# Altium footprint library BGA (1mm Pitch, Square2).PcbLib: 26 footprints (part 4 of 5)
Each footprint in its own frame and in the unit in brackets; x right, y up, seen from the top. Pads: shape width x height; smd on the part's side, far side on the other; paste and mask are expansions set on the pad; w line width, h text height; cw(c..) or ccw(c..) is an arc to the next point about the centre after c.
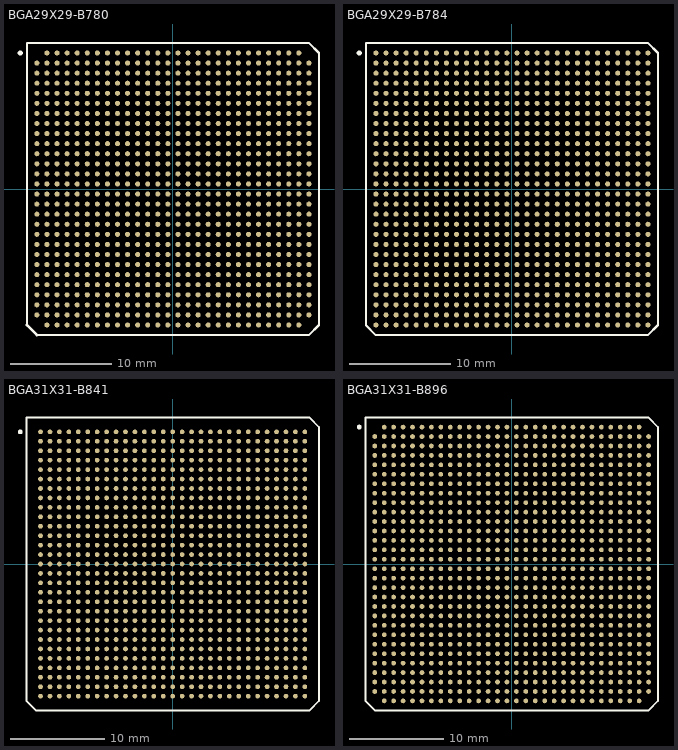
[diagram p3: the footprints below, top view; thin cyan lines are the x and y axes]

## BGA29X29-B780 [mm]
pads (780):
  round 0.5 smd: A2(-12.5,13.5) A3(-11.5,13.5) A4(-10.5,13.5) A5(-9.5,13.5) A6(-8.5,13.5) A7(-7.5,13.5) A8(-6.5,13.5) A9(-5.5,13.5) A10(-4.5,13.5) A11(-3.5,13.5) A12(-2.5,13.5) A13(-1.5,13.5) A14(-0.5,13.5) A15(0.5,13.5) A16(1.5,13.5) A17(2.5,13.5) A18(3.5,13.5) A19(4.5,13.5) A20(5.5,13.5) A21(6.5,13.5) A22(7.5,13.5) A23(8.5,13.5) A24(9.5,13.5) A25(10.5,13.5) A26(11.5,13.5) A27(12.5,13.5) AA1(-13.5,-6.5) AA2(-12.5,-6.5) AA3(-11.5,-6.5) AA4(-10.5,-6.5) AA5(-9.5,-6.5) AA6(-8.5,-6.5) AA7(-7.5,-6.5) AA8(-6.5,-6.5) AA9(-5.5,-6.5) AA10(-4.5,-6.5) AA11(-3.5,-6.5) AA12(-2.5,-6.5) AA13(-1.5,-6.5) AA14(-0.5,-6.5) AA15(0.5,-6.5) AA16(1.5,-6.5) AA17(2.5,-6.5) AA18(3.5,-6.5) AA19(4.5,-6.5) AA20(5.5,-6.5) AA21(6.5,-6.5) AA22(7.5,-6.5) AA23(8.5,-6.5) AA24(9.5,-6.5) AA25(10.5,-6.5) AA26(11.5,-6.5) AA27(12.5,-6.5) AA28(13.5,-6.5) AB1(-13.5,-7.5) AB2(-12.5,-7.5) AB3(-11.5,-7.5) AB4(-10.5,-7.5) AB5(-9.5,-7.5) AB6(-8.5,-7.5) AB7(-7.5,-7.5) AB8(-6.5,-7.5) AB9(-5.5,-7.5) AB10(-4.5,-7.5) AB11(-3.5,-7.5) AB12(-2.5,-7.5) AB13(-1.5,-7.5) AB14(-0.5,-7.5) AB15(0.5,-7.5) AB16(1.5,-7.5) AB17(2.5,-7.5) AB18(3.5,-7.5) AB19(4.5,-7.5) AB20(5.5,-7.5) AB21(6.5,-7.5) AB22(7.5,-7.5) AB23(8.5,-7.5) AB24(9.5,-7.5) AB25(10.5,-7.5) AB26(11.5,-7.5) AB27(12.5,-7.5) AB28(13.5,-7.5) AC1(-13.5,-8.5) AC2(-12.5,-8.5) AC3(-11.5,-8.5) AC4(-10.5,-8.5) AC5(-9.5,-8.5) AC6(-8.5,-8.5) AC7(-7.5,-8.5) AC8(-6.5,-8.5) AC9(-5.5,-8.5) AC10(-4.5,-8.5) AC11(-3.5,-8.5) AC12(-2.5,-8.5) AC13(-1.5,-8.5) AC14(-0.5,-8.5) AC15(0.5,-8.5) AC16(1.5,-8.5) AC17(2.5,-8.5) AC18(3.5,-8.5) AC19(4.5,-8.5) AC20(5.5,-8.5) AC21(6.5,-8.5) AC22(7.5,-8.5) AC23(8.5,-8.5) AC24(9.5,-8.5) AC25(10.5,-8.5) AC26(11.5,-8.5) AC27(12.5,-8.5) AC28(13.5,-8.5) AD1(-13.5,-9.5) AD2(-12.5,-9.5) AD3(-11.5,-9.5) AD4(-10.5,-9.5) AD5(-9.5,-9.5) AD6(-8.5,-9.5) AD7(-7.5,-9.5) AD8(-6.5,-9.5) AD9(-5.5,-9.5) AD10(-4.5,-9.5) AD11(-3.5,-9.5) AD12(-2.5,-9.5) AD13(-1.5,-9.5) AD14(-0.5,-9.5) AD15(0.5,-9.5) AD16(1.5,-9.5) AD17(2.5,-9.5) AD18(3.5,-9.5) AD19(4.5,-9.5) AD20(5.5,-9.5) AD21(6.5,-9.5) AD22(7.5,-9.5) AD23(8.5,-9.5) AD24(9.5,-9.5) AD25(10.5,-9.5) AD26(11.5,-9.5) AD27(12.5,-9.5) AD28(13.5,-9.5) AE1(-13.5,-10.5) AE2(-12.5,-10.5) AE3(-11.5,-10.5) AE4(-10.5,-10.5) AE5(-9.5,-10.5) AE6(-8.5,-10.5) AE7(-7.5,-10.5) AE8(-6.5,-10.5) AE9(-5.5,-10.5) AE10(-4.5,-10.5) AE11(-3.5,-10.5) AE12(-2.5,-10.5) AE13(-1.5,-10.5) AE14(-0.5,-10.5) AE15(0.5,-10.5) AE16(1.5,-10.5) AE17(2.5,-10.5) AE18(3.5,-10.5) AE19(4.5,-10.5) AE20(5.5,-10.5) AE21(6.5,-10.5) AE22(7.5,-10.5) AE23(8.5,-10.5) AE24(9.5,-10.5) AE25(10.5,-10.5) AE26(11.5,-10.5) AE27(12.5,-10.5) AE28(13.5,-10.5) AF1(-13.5,-11.5) AF2(-12.5,-11.5) AF3(-11.5,-11.5) AF4(-10.5,-11.5) AF5(-9.5,-11.5) AF6(-8.5,-11.5) AF7(-7.5,-11.5) AF8(-6.5,-11.5) AF9(-5.5,-11.5) AF10(-4.5,-11.5) AF11(-3.5,-11.5) AF12(-2.5,-11.5) AF13(-1.5,-11.5) AF14(-0.5,-11.5) AF15(0.5,-11.5) AF16(1.5,-11.5) AF17(2.5,-11.5) AF18(3.5,-11.5) AF19(4.5,-11.5) AF20(5.5,-11.5) AF21(6.5,-11.5) AF22(7.5,-11.5) AF23(8.5,-11.5) AF24(9.5,-11.5) AF25(10.5,-11.5) AF26(11.5,-11.5) AF27(12.5,-11.5) AF28(13.5,-11.5) AG1(-13.5,-12.5) AG2(-12.5,-12.5) AG3(-11.5,-12.5) AG4(-10.5,-12.5) AG5(-9.5,-12.5) AG6(-8.5,-12.5) AG7(-7.5,-12.5) AG8(-6.5,-12.5) AG9(-5.5,-12.5) AG10(-4.5,-12.5) AG11(-3.5,-12.5) AG12(-2.5,-12.5) AG13(-1.5,-12.5) AG14(-0.5,-12.5) AG15(0.5,-12.5) AG16(1.5,-12.5) AG17(2.5,-12.5) AG18(3.5,-12.5) AG19(4.5,-12.5) AG20(5.5,-12.5) AG21(6.5,-12.5) AG22(7.5,-12.5) AG23(8.5,-12.5) AG24(9.5,-12.5) AG25(10.5,-12.5) AG26(11.5,-12.5) AG27(12.5,-12.5) AG28(13.5,-12.5) AH2(-12.5,-13.5) AH3(-11.5,-13.5) AH4(-10.5,-13.5) AH5(-9.5,-13.5) AH6(-8.5,-13.5) AH7(-7.5,-13.5) AH8(-6.5,-13.5) AH9(-5.5,-13.5) AH10(-4.5,-13.5) AH11(-3.5,-13.5) AH12(-2.5,-13.5) AH13(-1.5,-13.5) AH14(-0.5,-13.5) AH15(0.5,-13.5) AH16(1.5,-13.5) AH17(2.5,-13.5) AH18(3.5,-13.5) AH19(4.5,-13.5) AH20(5.5,-13.5) AH21(6.5,-13.5) AH22(7.5,-13.5) AH23(8.5,-13.5) AH24(9.5,-13.5) AH25(10.5,-13.5) AH26(11.5,-13.5) AH27(12.5,-13.5) B1(-13.5,12.5) B2(-12.5,12.5) B3(-11.5,12.5) B4(-10.5,12.5) B5(-9.5,12.5) B6(-8.5,12.5) B7(-7.5,12.5) B8(-6.5,12.5) B9(-5.5,12.5) B10(-4.5,12.5) B11(-3.5,12.5) B12(-2.5,12.5) B13(-1.5,12.5) B14(-0.5,12.5) B15(0.5,12.5) B16(1.5,12.5) B17(2.5,12.5) B18(3.5,12.5) B19(4.5,12.5) B20(5.5,12.5) B21(6.5,12.5) B22(7.5,12.5) B23(8.5,12.5) B24(9.5,12.5) B25(10.5,12.5) B26(11.5,12.5) B27(12.5,12.5) B28(13.5,12.5) C1(-13.5,11.5) C2(-12.5,11.5) C3(-11.5,11.5) C4(-10.5,11.5) C5(-9.5,11.5) C6(-8.5,11.5) C7(-7.5,11.5) C8(-6.5,11.5) C9(-5.5,11.5) C10(-4.5,11.5) C11(-3.5,11.5) C12(-2.5,11.5) C13(-1.5,11.5) C14(-0.5,11.5) C15(0.5,11.5) C16(1.5,11.5) C17(2.5,11.5) C18(3.5,11.5) C19(4.5,11.5) C20(5.5,11.5) C21(6.5,11.5) C22(7.5,11.5) C23(8.5,11.5) C24(9.5,11.5) C25(10.5,11.5) C26(11.5,11.5) C27(12.5,11.5) C28(13.5,11.5) D1(-13.5,10.5) D2(-12.5,10.5) D3(-11.5,10.5) D4(-10.5,10.5) D5(-9.5,10.5) D6(-8.5,10.5) D7(-7.5,10.5) D8(-6.5,10.5) D9(-5.5,10.5) D10(-4.5,10.5) D11(-3.5,10.5) D12(-2.5,10.5) D13(-1.5,10.5) D14(-0.5,10.5) D15(0.5,10.5) D16(1.5,10.5) D17(2.5,10.5) D18(3.5,10.5) D19(4.5,10.5) D20(5.5,10.5) D21(6.5,10.5) D22(7.5,10.5) D23(8.5,10.5) D24(9.5,10.5) D25(10.5,10.5) D26(11.5,10.5) D27(12.5,10.5) D28(13.5,10.5) E1(-13.5,9.5) E2(-12.5,9.5) E3(-11.5,9.5) E4(-10.5,9.5) E5(-9.5,9.5) E6(-8.5,9.5) E7(-7.5,9.5) E8(-6.5,9.5) E9(-5.5,9.5) E10(-4.5,9.5) E11(-3.5,9.5) E12(-2.5,9.5) E13(-1.5,9.5) E14(-0.5,9.5) E15(0.5,9.5) E16(1.5,9.5) E17(2.5,9.5) E18(3.5,9.5) E19(4.5,9.5) E20(5.5,9.5) E21(6.5,9.5) E22(7.5,9.5) E23(8.5,9.5) E24(9.5,9.5) E25(10.5,9.5) E26(11.5,9.5) E27(12.5,9.5) E28(13.5,9.5) F1(-13.5,8.5) F2(-12.5,8.5) F3(-11.5,8.5) F4(-10.5,8.5) F5(-9.5,8.5) F6(-8.5,8.5) F7(-7.5,8.5) F8(-6.5,8.5) F9(-5.5,8.5) F10(-4.5,8.5) F11(-3.5,8.5) F12(-2.5,8.5) F13(-1.5,8.5) F14(-0.5,8.5) F15(0.5,8.5) F16(1.5,8.5) F17(2.5,8.5) F18(3.5,8.5) F19(4.5,8.5) F20(5.5,8.5) F21(6.5,8.5) F22(7.5,8.5) F23(8.5,8.5) F24(9.5,8.5) F25(10.5,8.5) F26(11.5,8.5) F27(12.5,8.5) F28(13.5,8.5) G1(-13.5,7.5) G2(-12.5,7.5) G3(-11.5,7.5) G4(-10.5,7.5) G5(-9.5,7.5) G6(-8.5,7.5) G7(-7.5,7.5) G8(-6.5,7.5) G9(-5.5,7.5) G10(-4.5,7.5) G11(-3.5,7.5) G12(-2.5,7.5) G13(-1.5,7.5) G14(-0.5,7.5) G15(0.5,7.5) G16(1.5,7.5) G17(2.5,7.5) G18(3.5,7.5) G19(4.5,7.5) G20(5.5,7.5) G21(6.5,7.5) G22(7.5,7.5) G23(8.5,7.5) G24(9.5,7.5) G25(10.5,7.5) G26(11.5,7.5) G27(12.5,7.5) G28(13.5,7.5) H1(-13.5,6.5) H2(-12.5,6.5) H3(-11.5,6.5) H4(-10.5,6.5) H5(-9.5,6.5) H6(-8.5,6.5) H7(-7.5,6.5) H8(-6.5,6.5) H9(-5.5,6.5) H10(-4.5,6.5) H11(-3.5,6.5) H12(-2.5,6.5) H13(-1.5,6.5) H14(-0.5,6.5) H15(0.5,6.5) H16(1.5,6.5) H17(2.5,6.5) H18(3.5,6.5) H19(4.5,6.5) H20(5.5,6.5) H21(6.5,6.5) H22(7.5,6.5) H23(8.5,6.5) H24(9.5,6.5) H25(10.5,6.5) H26(11.5,6.5) H27(12.5,6.5) H28(13.5,6.5) J1(-13.5,5.5) J2(-12.5,5.5) J3(-11.5,5.5) J4(-10.5,5.5) J5(-9.5,5.5) J6(-8.5,5.5) J7(-7.5,5.5) J8(-6.5,5.5) J9(-5.5,5.5) J10(-4.5,5.5) J11(-3.5,5.5) J12(-2.5,5.5) J13(-1.5,5.5) J14(-0.5,5.5) J15(0.5,5.5) J16(1.5,5.5) J17(2.5,5.5) J18(3.5,5.5) J19(4.5,5.5) J20(5.5,5.5) J21(6.5,5.5) J22(7.5,5.5) J23(8.5,5.5) J24(9.5,5.5) J25(10.5,5.5) J26(11.5,5.5) J27(12.5,5.5) J28(13.5,5.5) K1(-13.5,4.5) K2(-12.5,4.5) K3(-11.5,4.5) K4(-10.5,4.5) K5(-9.5,4.5) K6(-8.5,4.5) K7(-7.5,4.5) K8(-6.5,4.5) K9(-5.5,4.5) K10(-4.5,4.5) K11(-3.5,4.5) K12(-2.5,4.5) K13(-1.5,4.5) K14(-0.5,4.5) K15(0.5,4.5) K16(1.5,4.5) K17(2.5,4.5) K18(3.5,4.5) K19(4.5,4.5) K20(5.5,4.5) K21(6.5,4.5) K22(7.5,4.5) K23(8.5,4.5) K24(9.5,4.5) K25(10.5,4.5) K26(11.5,4.5) K27(12.5,4.5) K28(13.5,4.5) L1(-13.5,3.5) L2(-12.5,3.5) L3(-11.5,3.5) L4(-10.5,3.5) L5(-9.5,3.5) L6(-8.5,3.5) L7(-7.5,3.5) L8(-6.5,3.5) L9(-5.5,3.5) L10(-4.5,3.5) L11(-3.5,3.5) L12(-2.5,3.5) L13(-1.5,3.5) L14(-0.5,3.5) L15(0.5,3.5) L16(1.5,3.5) L17(2.5,3.5) L18(3.5,3.5) L19(4.5,3.5) L20(5.5,3.5) L21(6.5,3.5) L22(7.5,3.5) L23(8.5,3.5) L24(9.5,3.5) L25(10.5,3.5) L26(11.5,3.5) L27(12.5,3.5) L28(13.5,3.5) M1(-13.5,2.5) M2(-12.5,2.5) M3(-11.5,2.5) M4(-10.5,2.5) M5(-9.5,2.5) M6(-8.5,2.5) M7(-7.5,2.5) M8(-6.5,2.5) M9(-5.5,2.5) M10(-4.5,2.5) M11(-3.5,2.5) M12(-2.5,2.5) M13(-1.5,2.5) M14(-0.5,2.5) M15(0.5,2.5) M16(1.5,2.5) M17(2.5,2.5) M18(3.5,2.5) M19(4.5,2.5) M20(5.5,2.5) M21(6.5,2.5) M22(7.5,2.5) M23(8.5,2.5) M24(9.5,2.5) M25(10.5,2.5) M26(11.5,2.5) M27(12.5,2.5) M28(13.5,2.5) N1(-13.5,1.5) N2(-12.5,1.5) N3(-11.5,1.5) N4(-10.5,1.5) N5(-9.5,1.5) N6(-8.5,1.5) N7(-7.5,1.5) N8(-6.5,1.5) N9(-5.5,1.5) N10(-4.5,1.5) N11(-3.5,1.5) N12(-2.5,1.5) N13(-1.5,1.5) N14(-0.5,1.5) N15(0.5,1.5) N16(1.5,1.5) N17(2.5,1.5) N18(3.5,1.5) N19(4.5,1.5) N20(5.5,1.5) N21(6.5,1.5) N22(7.5,1.5) N23(8.5,1.5) N24(9.5,1.5) N25(10.5,1.5) N26(11.5,1.5) N27(12.5,1.5) N28(13.5,1.5) P1(-13.5,0.5) P2(-12.5,0.5) P3(-11.5,0.5) P4(-10.5,0.5) P5(-9.5,0.5) P6(-8.5,0.5) P7(-7.5,0.5) P8(-6.5,0.5) P9(-5.5,0.5) P10(-4.5,0.5) P11(-3.5,0.5) P12(-2.5,0.5) P13(-1.5,0.5) P14(-0.5,0.5) P15(0.5,0.5) P16(1.5,0.5) P17(2.5,0.5) P18(3.5,0.5) P19(4.5,0.5) P20(5.5,0.5) P21(6.5,0.5) P22(7.5,0.5) P23(8.5,0.5) P24(9.5,0.5) P25(10.5,0.5) P26(11.5,0.5) P27(12.5,0.5) P28(13.5,0.5) R1(-13.5,-0.5) R2(-12.5,-0.5) R3(-11.5,-0.5) R4(-10.5,-0.5) R5(-9.5,-0.5) R6(-8.5,-0.5) R7(-7.5,-0.5) R8(-6.5,-0.5) R9(-5.5,-0.5) R10(-4.5,-0.5) R11(-3.5,-0.5) R12(-2.5,-0.5) R13(-1.5,-0.5) R14(-0.5,-0.5) R15(0.5,-0.5) R16(1.5,-0.5) R17(2.5,-0.5) R18(3.5,-0.5) R19(4.5,-0.5) R20(5.5,-0.5) R21(6.5,-0.5) R22(7.5,-0.5) R23(8.5,-0.5) R24(9.5,-0.5) R25(10.5,-0.5) R26(11.5,-0.5) R27(12.5,-0.5) R28(13.5,-0.5) T1(-13.5,-1.5) T2(-12.5,-1.5) T3(-11.5,-1.5) T4(-10.5,-1.5) T5(-9.5,-1.5) T6(-8.5,-1.5) T7(-7.5,-1.5) T8(-6.5,-1.5) T9(-5.5,-1.5) T10(-4.5,-1.5) T11(-3.5,-1.5) T12(-2.5,-1.5) T13(-1.5,-1.5) T14(-0.5,-1.5) T15(0.5,-1.5) T16(1.5,-1.5) T17(2.5,-1.5) T18(3.5,-1.5) T19(4.5,-1.5) T20(5.5,-1.5) T21(6.5,-1.5) T22(7.5,-1.5) T23(8.5,-1.5) T24(9.5,-1.5) T25(10.5,-1.5) T26(11.5,-1.5) T27(12.5,-1.5) T28(13.5,-1.5) U1(-13.5,-2.5) U2(-12.5,-2.5) U3(-11.5,-2.5) U4(-10.5,-2.5) U5(-9.5,-2.5) U6(-8.5,-2.5) U7(-7.5,-2.5) U8(-6.5,-2.5) U9(-5.5,-2.5) U10(-4.5,-2.5) U11(-3.5,-2.5) U12(-2.5,-2.5) U13(-1.5,-2.5) U14(-0.5,-2.5) U15(0.5,-2.5) U16(1.5,-2.5) U17(2.5,-2.5) U18(3.5,-2.5) U19(4.5,-2.5) U20(5.5,-2.5) U21(6.5,-2.5) U22(7.5,-2.5) U23(8.5,-2.5) U24(9.5,-2.5) U25(10.5,-2.5) U26(11.5,-2.5) U27(12.5,-2.5) U28(13.5,-2.5) V1(-13.5,-3.5) V2(-12.5,-3.5) V3(-11.5,-3.5) V4(-10.5,-3.5) V5(-9.5,-3.5) V6(-8.5,-3.5) V7(-7.5,-3.5) V8(-6.5,-3.5) V9(-5.5,-3.5) V10(-4.5,-3.5) V11(-3.5,-3.5) V12(-2.5,-3.5) V13(-1.5,-3.5) V14(-0.5,-3.5) V15(0.5,-3.5) V16(1.5,-3.5) V17(2.5,-3.5) V18(3.5,-3.5) V19(4.5,-3.5) V20(5.5,-3.5) V21(6.5,-3.5) V22(7.5,-3.5) V23(8.5,-3.5) V24(9.5,-3.5) V25(10.5,-3.5) V26(11.5,-3.5) V27(12.5,-3.5) V28(13.5,-3.5) W1(-13.5,-4.5) W2(-12.5,-4.5) W3(-11.5,-4.5) W4(-10.5,-4.5) W5(-9.5,-4.5) W6(-8.5,-4.5) W7(-7.5,-4.5) W8(-6.5,-4.5) W9(-5.5,-4.5) W10(-4.5,-4.5) W11(-3.5,-4.5) W12(-2.5,-4.5) W13(-1.5,-4.5) W14(-0.5,-4.5) W15(0.5,-4.5) W16(1.5,-4.5) W17(2.5,-4.5) W18(3.5,-4.5) W19(4.5,-4.5) W20(5.5,-4.5) W21(6.5,-4.5) W22(7.5,-4.5) W23(8.5,-4.5) W24(9.5,-4.5) W25(10.5,-4.5) W26(11.5,-4.5) W27(12.5,-4.5) W28(13.5,-4.5) Y1(-13.5,-5.5) Y2(-12.5,-5.5) Y3(-11.5,-5.5) Y4(-10.5,-5.5) Y5(-9.5,-5.5) Y6(-8.5,-5.5) Y7(-7.5,-5.5) Y8(-6.5,-5.5) Y9(-5.5,-5.5) Y10(-4.5,-5.5) Y11(-3.5,-5.5) Y12(-2.5,-5.5) Y13(-1.5,-5.5) Y14(-0.5,-5.5) Y15(0.5,-5.5) Y16(1.5,-5.5) Y17(2.5,-5.5) Y18(3.5,-5.5) Y19(4.5,-5.5) Y20(5.5,-5.5) Y21(6.5,-5.5) Y22(7.5,-5.5) Y23(8.5,-5.5) Y24(9.5,-5.5) Y25(10.5,-5.5) Y26(11.5,-5.5) Y27(12.5,-5.5) Y28(13.5,-5.5)
Top Overlay:
  circle w0.25: c-15.15,13.5 r0.125
  lines w0.2: -14.5,-13.5 -14.5,14.5 13.5,14.5 14.5,13.5 14.5,-13.5 13.5,-14.5 -13.5,-14.5
  lines w0.254: -14.5,-13.5 -13.5,-14.5

## BGA29X29-B784 [mm]
pads (784):
  round 0.5 smd: A1(-13.5,13.5) A2(-12.5,13.5) A3(-11.5,13.5) A4(-10.5,13.5) A5(-9.5,13.5) A6(-8.5,13.5) A7(-7.5,13.5) A8(-6.5,13.5) A9(-5.5,13.5) A10(-4.5,13.5) A11(-3.5,13.5) A12(-2.5,13.5) A13(-1.5,13.5) A14(-0.5,13.5) A15(0.5,13.5) A16(1.5,13.5) A17(2.5,13.5) A18(3.5,13.5) A19(4.5,13.5) A20(5.5,13.5) A21(6.5,13.5) A22(7.5,13.5) A23(8.5,13.5) A24(9.5,13.5) A25(10.5,13.5) A26(11.5,13.5) A27(12.5,13.5) A28(13.5,13.5) AA1(-13.5,-6.5) AA2(-12.5,-6.5) AA3(-11.5,-6.5) AA4(-10.5,-6.5) AA5(-9.5,-6.5) AA6(-8.5,-6.5) AA7(-7.5,-6.5) AA8(-6.5,-6.5) AA9(-5.5,-6.5) AA10(-4.5,-6.5) AA11(-3.5,-6.5) AA12(-2.5,-6.5) AA13(-1.5,-6.5) AA14(-0.5,-6.5) AA15(0.5,-6.5) AA16(1.5,-6.5) AA17(2.5,-6.5) AA18(3.5,-6.5) AA19(4.5,-6.5) AA20(5.5,-6.5) AA21(6.5,-6.5) AA22(7.5,-6.5) AA23(8.5,-6.5) AA24(9.5,-6.5) AA25(10.5,-6.5) AA26(11.5,-6.5) AA27(12.5,-6.5) AA28(13.5,-6.5) AB1(-13.5,-7.5) AB2(-12.5,-7.5) AB3(-11.5,-7.5) AB4(-10.5,-7.5) AB5(-9.5,-7.5) AB6(-8.5,-7.5) AB7(-7.5,-7.5) AB8(-6.5,-7.5) AB9(-5.5,-7.5) AB10(-4.5,-7.5) AB11(-3.5,-7.5) AB12(-2.5,-7.5) AB13(-1.5,-7.5) AB14(-0.5,-7.5) AB15(0.5,-7.5) AB16(1.5,-7.5) AB17(2.5,-7.5) AB18(3.5,-7.5) AB19(4.5,-7.5) AB20(5.5,-7.5) AB21(6.5,-7.5) AB22(7.5,-7.5) AB23(8.5,-7.5) AB24(9.5,-7.5) AB25(10.5,-7.5) AB26(11.5,-7.5) AB27(12.5,-7.5) AB28(13.5,-7.5) AC1(-13.5,-8.5) AC2(-12.5,-8.5) AC3(-11.5,-8.5) AC4(-10.5,-8.5) AC5(-9.5,-8.5) AC6(-8.5,-8.5) AC7(-7.5,-8.5) AC8(-6.5,-8.5) AC9(-5.5,-8.5) AC10(-4.5,-8.5) AC11(-3.5,-8.5) AC12(-2.5,-8.5) AC13(-1.5,-8.5) AC14(-0.5,-8.5) AC15(0.5,-8.5) AC16(1.5,-8.5) AC17(2.5,-8.5) AC18(3.5,-8.5) AC19(4.5,-8.5) AC20(5.5,-8.5) AC21(6.5,-8.5) AC22(7.5,-8.5) AC23(8.5,-8.5) AC24(9.5,-8.5) AC25(10.5,-8.5) AC26(11.5,-8.5) AC27(12.5,-8.5) AC28(13.5,-8.5) AD1(-13.5,-9.5) AD2(-12.5,-9.5) AD3(-11.5,-9.5) AD4(-10.5,-9.5) AD5(-9.5,-9.5) AD6(-8.5,-9.5) AD7(-7.5,-9.5) AD8(-6.5,-9.5) AD9(-5.5,-9.5) AD10(-4.5,-9.5) AD11(-3.5,-9.5) AD12(-2.5,-9.5) AD13(-1.5,-9.5) AD14(-0.5,-9.5) AD15(0.5,-9.5) AD16(1.5,-9.5) AD17(2.5,-9.5) AD18(3.5,-9.5) AD19(4.5,-9.5) AD20(5.5,-9.5) AD21(6.5,-9.5) AD22(7.5,-9.5) AD23(8.5,-9.5) AD24(9.5,-9.5) AD25(10.5,-9.5) AD26(11.5,-9.5) AD27(12.5,-9.5) AD28(13.5,-9.5) AE1(-13.5,-10.5) AE2(-12.5,-10.5) AE3(-11.5,-10.5) AE4(-10.5,-10.5) AE5(-9.5,-10.5) AE6(-8.5,-10.5) AE7(-7.5,-10.5) AE8(-6.5,-10.5) AE9(-5.5,-10.5) AE10(-4.5,-10.5) AE11(-3.5,-10.5) AE12(-2.5,-10.5) AE13(-1.5,-10.5) AE14(-0.5,-10.5) AE15(0.5,-10.5) AE16(1.5,-10.5) AE17(2.5,-10.5) AE18(3.5,-10.5) AE19(4.5,-10.5) AE20(5.5,-10.5) AE21(6.5,-10.5) AE22(7.5,-10.5) AE23(8.5,-10.5) AE24(9.5,-10.5) AE25(10.5,-10.5) AE26(11.5,-10.5) AE27(12.5,-10.5) AE28(13.5,-10.5) AF1(-13.5,-11.5) AF2(-12.5,-11.5) AF3(-11.5,-11.5) AF4(-10.5,-11.5) AF5(-9.5,-11.5) AF6(-8.5,-11.5) AF7(-7.5,-11.5) AF8(-6.5,-11.5) AF9(-5.5,-11.5) AF10(-4.5,-11.5) AF11(-3.5,-11.5) AF12(-2.5,-11.5) AF13(-1.5,-11.5) AF14(-0.5,-11.5) AF15(0.5,-11.5) AF16(1.5,-11.5) AF17(2.5,-11.5) AF18(3.5,-11.5) AF19(4.5,-11.5) AF20(5.5,-11.5) AF21(6.5,-11.5) AF22(7.5,-11.5) AF23(8.5,-11.5) AF24(9.5,-11.5) AF25(10.5,-11.5) AF26(11.5,-11.5) AF27(12.5,-11.5) AF28(13.5,-11.5) AG1(-13.5,-12.5) AG2(-12.5,-12.5) AG3(-11.5,-12.5) AG4(-10.5,-12.5) AG5(-9.5,-12.5) AG6(-8.5,-12.5) AG7(-7.5,-12.5) AG8(-6.5,-12.5) AG9(-5.5,-12.5) AG10(-4.5,-12.5) AG11(-3.5,-12.5) AG12(-2.5,-12.5) AG13(-1.5,-12.5) AG14(-0.5,-12.5) AG15(0.5,-12.5) AG16(1.5,-12.5) AG17(2.5,-12.5) AG18(3.5,-12.5) AG19(4.5,-12.5) AG20(5.5,-12.5) AG21(6.5,-12.5) AG22(7.5,-12.5) AG23(8.5,-12.5) AG24(9.5,-12.5) AG25(10.5,-12.5) AG26(11.5,-12.5) AG27(12.5,-12.5) AG28(13.5,-12.5) AH1(-13.5,-13.5) AH2(-12.5,-13.5) AH3(-11.5,-13.5) AH4(-10.5,-13.5) AH5(-9.5,-13.5) AH6(-8.5,-13.5) AH7(-7.5,-13.5) AH8(-6.5,-13.5) AH9(-5.5,-13.5) AH10(-4.5,-13.5) AH11(-3.5,-13.5) AH12(-2.5,-13.5) AH13(-1.5,-13.5) AH14(-0.5,-13.5) AH15(0.5,-13.5) AH16(1.5,-13.5) AH17(2.5,-13.5) AH18(3.5,-13.5) AH19(4.5,-13.5) AH20(5.5,-13.5) AH21(6.5,-13.5) AH22(7.5,-13.5) AH23(8.5,-13.5) AH24(9.5,-13.5) AH25(10.5,-13.5) AH26(11.5,-13.5) AH27(12.5,-13.5) AH28(13.5,-13.5) B1(-13.5,12.5) B2(-12.5,12.5) B3(-11.5,12.5) B4(-10.5,12.5) B5(-9.5,12.5) B6(-8.5,12.5) B7(-7.5,12.5) B8(-6.5,12.5) B9(-5.5,12.5) B10(-4.5,12.5) B11(-3.5,12.5) B12(-2.5,12.5) B13(-1.5,12.5) B14(-0.5,12.5) B15(0.5,12.5) B16(1.5,12.5) B17(2.5,12.5) B18(3.5,12.5) B19(4.5,12.5) B20(5.5,12.5) B21(6.5,12.5) B22(7.5,12.5) B23(8.5,12.5) B24(9.5,12.5) B25(10.5,12.5) B26(11.5,12.5) B27(12.5,12.5) B28(13.5,12.5) C1(-13.5,11.5) C2(-12.5,11.5) C3(-11.5,11.5) C4(-10.5,11.5) C5(-9.5,11.5) C6(-8.5,11.5) C7(-7.5,11.5) C8(-6.5,11.5) C9(-5.5,11.5) C10(-4.5,11.5) C11(-3.5,11.5) C12(-2.5,11.5) C13(-1.5,11.5) C14(-0.5,11.5) C15(0.5,11.5) C16(1.5,11.5) C17(2.5,11.5) C18(3.5,11.5) C19(4.5,11.5) C20(5.5,11.5) C21(6.5,11.5) C22(7.5,11.5) C23(8.5,11.5) C24(9.5,11.5) C25(10.5,11.5) C26(11.5,11.5) C27(12.5,11.5) C28(13.5,11.5) D1(-13.5,10.5) D2(-12.5,10.5) D3(-11.5,10.5) D4(-10.5,10.5) D5(-9.5,10.5) D6(-8.5,10.5) D7(-7.5,10.5) D8(-6.5,10.5) D9(-5.5,10.5) D10(-4.5,10.5) D11(-3.5,10.5) D12(-2.5,10.5) D13(-1.5,10.5) D14(-0.5,10.5) D15(0.5,10.5) D16(1.5,10.5) D17(2.5,10.5) D18(3.5,10.5) D19(4.5,10.5) D20(5.5,10.5) D21(6.5,10.5) D22(7.5,10.5) D23(8.5,10.5) D24(9.5,10.5) D25(10.5,10.5) D26(11.5,10.5) D27(12.5,10.5) D28(13.5,10.5) E1(-13.5,9.5) E2(-12.5,9.5) E3(-11.5,9.5) E4(-10.5,9.5) E5(-9.5,9.5) E6(-8.5,9.5) E7(-7.5,9.5) E8(-6.5,9.5) E9(-5.5,9.5) E10(-4.5,9.5) E11(-3.5,9.5) E12(-2.5,9.5) E13(-1.5,9.5) E14(-0.5,9.5) E15(0.5,9.5) E16(1.5,9.5) E17(2.5,9.5) E18(3.5,9.5) E19(4.5,9.5) E20(5.5,9.5) E21(6.5,9.5) E22(7.5,9.5) E23(8.5,9.5) E24(9.5,9.5) E25(10.5,9.5) E26(11.5,9.5) E27(12.5,9.5) E28(13.5,9.5) F1(-13.5,8.5) F2(-12.5,8.5) F3(-11.5,8.5) F4(-10.5,8.5) F5(-9.5,8.5) F6(-8.5,8.5) F7(-7.5,8.5) F8(-6.5,8.5) F9(-5.5,8.5) F10(-4.5,8.5) F11(-3.5,8.5) F12(-2.5,8.5) F13(-1.5,8.5) F14(-0.5,8.5) F15(0.5,8.5) F16(1.5,8.5) F17(2.5,8.5) F18(3.5,8.5) F19(4.5,8.5) F20(5.5,8.5) F21(6.5,8.5) F22(7.5,8.5) F23(8.5,8.5) F24(9.5,8.5) F25(10.5,8.5) F26(11.5,8.5) F27(12.5,8.5) F28(13.5,8.5) G1(-13.5,7.5) G2(-12.5,7.5) G3(-11.5,7.5) G4(-10.5,7.5) G5(-9.5,7.5) G6(-8.5,7.5) G7(-7.5,7.5) G8(-6.5,7.5) G9(-5.5,7.5) G10(-4.5,7.5) G11(-3.5,7.5) G12(-2.5,7.5) G13(-1.5,7.5) G14(-0.5,7.5) G15(0.5,7.5) G16(1.5,7.5) G17(2.5,7.5) G18(3.5,7.5) G19(4.5,7.5) G20(5.5,7.5) G21(6.5,7.5) G22(7.5,7.5) G23(8.5,7.5) G24(9.5,7.5) G25(10.5,7.5) G26(11.5,7.5) G27(12.5,7.5) G28(13.5,7.5) H1(-13.5,6.5) H2(-12.5,6.5) H3(-11.5,6.5) H4(-10.5,6.5) H5(-9.5,6.5) H6(-8.5,6.5) H7(-7.5,6.5) H8(-6.5,6.5) H9(-5.5,6.5) H10(-4.5,6.5) H11(-3.5,6.5) H12(-2.5,6.5) H13(-1.5,6.5) H14(-0.5,6.5) H15(0.5,6.5) H16(1.5,6.5) H17(2.5,6.5) H18(3.5,6.5) H19(4.5,6.5) H20(5.5,6.5) H21(6.5,6.5) H22(7.5,6.5) H23(8.5,6.5) H24(9.5,6.5) H25(10.5,6.5) H26(11.5,6.5) H27(12.5,6.5) H28(13.5,6.5) J1(-13.5,5.5) J2(-12.5,5.5) J3(-11.5,5.5) J4(-10.5,5.5) J5(-9.5,5.5) J6(-8.5,5.5) J7(-7.5,5.5) J8(-6.5,5.5) J9(-5.5,5.5) J10(-4.5,5.5) J11(-3.5,5.5) J12(-2.5,5.5) J13(-1.5,5.5) J14(-0.5,5.5) J15(0.5,5.5) J16(1.5,5.5) J17(2.5,5.5) J18(3.5,5.5) J19(4.5,5.5) J20(5.5,5.5) J21(6.5,5.5) J22(7.5,5.5) J23(8.5,5.5) J24(9.5,5.5) J25(10.5,5.5) J26(11.5,5.5) J27(12.5,5.5) J28(13.5,5.5) K1(-13.5,4.5) K2(-12.5,4.5) K3(-11.5,4.5) K4(-10.5,4.5) K5(-9.5,4.5) K6(-8.5,4.5) K7(-7.5,4.5) K8(-6.5,4.5) K9(-5.5,4.5) K10(-4.5,4.5) K11(-3.5,4.5) K12(-2.5,4.5) K13(-1.5,4.5) K14(-0.5,4.5) K15(0.5,4.5) K16(1.5,4.5) K17(2.5,4.5) K18(3.5,4.5) K19(4.5,4.5) K20(5.5,4.5) K21(6.5,4.5) K22(7.5,4.5) K23(8.5,4.5) K24(9.5,4.5) K25(10.5,4.5) K26(11.5,4.5) K27(12.5,4.5) K28(13.5,4.5) L1(-13.5,3.5) L2(-12.5,3.5) L3(-11.5,3.5) L4(-10.5,3.5) L5(-9.5,3.5) L6(-8.5,3.5) L7(-7.5,3.5) L8(-6.5,3.5) L9(-5.5,3.5) L10(-4.5,3.5) L11(-3.5,3.5) L12(-2.5,3.5) L13(-1.5,3.5) L14(-0.5,3.5) L15(0.5,3.5) L16(1.5,3.5) L17(2.5,3.5) L18(3.5,3.5) L19(4.5,3.5) L20(5.5,3.5) L21(6.5,3.5) L22(7.5,3.5) L23(8.5,3.5) L24(9.5,3.5) L25(10.5,3.5) L26(11.5,3.5) L27(12.5,3.5) L28(13.5,3.5) M1(-13.5,2.5) M2(-12.5,2.5) M3(-11.5,2.5) M4(-10.5,2.5) M5(-9.5,2.5) M6(-8.5,2.5) M7(-7.5,2.5) M8(-6.5,2.5) M9(-5.5,2.5) M10(-4.5,2.5) M11(-3.5,2.5) M12(-2.5,2.5) M13(-1.5,2.5) M14(-0.5,2.5) M15(0.5,2.5) M16(1.5,2.5) M17(2.5,2.5) M18(3.5,2.5) M19(4.5,2.5) M20(5.5,2.5) M21(6.5,2.5) M22(7.5,2.5) M23(8.5,2.5) M24(9.5,2.5) M25(10.5,2.5) M26(11.5,2.5) M27(12.5,2.5) M28(13.5,2.5) N1(-13.5,1.5) N2(-12.5,1.5) N3(-11.5,1.5) N4(-10.5,1.5) N5(-9.5,1.5) N6(-8.5,1.5) N7(-7.5,1.5) N8(-6.5,1.5) N9(-5.5,1.5) N10(-4.5,1.5) N11(-3.5,1.5) N12(-2.5,1.5) N13(-1.5,1.5) N14(-0.5,1.5) N15(0.5,1.5) N16(1.5,1.5) N17(2.5,1.5) N18(3.5,1.5) N19(4.5,1.5) N20(5.5,1.5) N21(6.5,1.5) N22(7.5,1.5) N23(8.5,1.5) N24(9.5,1.5) N25(10.5,1.5) N26(11.5,1.5) N27(12.5,1.5) N28(13.5,1.5) P1(-13.5,0.5) P2(-12.5,0.5) P3(-11.5,0.5) P4(-10.5,0.5) P5(-9.5,0.5) P6(-8.5,0.5) P7(-7.5,0.5) P8(-6.5,0.5) P9(-5.5,0.5) P10(-4.5,0.5) P11(-3.5,0.5) P12(-2.5,0.5) P13(-1.5,0.5) P14(-0.5,0.5) P15(0.5,0.5) P16(1.5,0.5) P17(2.5,0.5) P18(3.5,0.5) P19(4.5,0.5) P20(5.5,0.5) P21(6.5,0.5) P22(7.5,0.5) P23(8.5,0.5) P24(9.5,0.5) P25(10.5,0.5) P26(11.5,0.5) P27(12.5,0.5) P28(13.5,0.5) R1(-13.5,-0.5) R2(-12.5,-0.5) R3(-11.5,-0.5) R4(-10.5,-0.5) R5(-9.5,-0.5) R6(-8.5,-0.5) R7(-7.5,-0.5) R8(-6.5,-0.5) R9(-5.5,-0.5) R10(-4.5,-0.5) R11(-3.5,-0.5) R12(-2.5,-0.5) R13(-1.5,-0.5) R14(-0.5,-0.5) R15(0.5,-0.5) R16(1.5,-0.5) R17(2.5,-0.5) R18(3.5,-0.5) R19(4.5,-0.5) R20(5.5,-0.5) R21(6.5,-0.5) R22(7.5,-0.5) R23(8.5,-0.5) R24(9.5,-0.5) R25(10.5,-0.5) R26(11.5,-0.5) R27(12.5,-0.5) R28(13.5,-0.5) T1(-13.5,-1.5) T2(-12.5,-1.5) T3(-11.5,-1.5) T4(-10.5,-1.5) T5(-9.5,-1.5) T6(-8.5,-1.5) T7(-7.5,-1.5) T8(-6.5,-1.5) T9(-5.5,-1.5) T10(-4.5,-1.5) T11(-3.5,-1.5) T12(-2.5,-1.5) T13(-1.5,-1.5) T14(-0.5,-1.5) T15(0.5,-1.5) T16(1.5,-1.5) T17(2.5,-1.5) T18(3.5,-1.5) T19(4.5,-1.5) T20(5.5,-1.5) T21(6.5,-1.5) T22(7.5,-1.5) T23(8.5,-1.5) T24(9.5,-1.5) T25(10.5,-1.5) T26(11.5,-1.5) T27(12.5,-1.5) T28(13.5,-1.5) U1(-13.5,-2.5) U2(-12.5,-2.5) U3(-11.5,-2.5) U4(-10.5,-2.5) U5(-9.5,-2.5) U6(-8.5,-2.5) U7(-7.5,-2.5) U8(-6.5,-2.5) U9(-5.5,-2.5) U10(-4.5,-2.5) U11(-3.5,-2.5) U12(-2.5,-2.5) U13(-1.5,-2.5) U14(-0.5,-2.5) U15(0.5,-2.5) U16(1.5,-2.5) U17(2.5,-2.5) U18(3.5,-2.5) U19(4.5,-2.5) U20(5.5,-2.5) U21(6.5,-2.5) U22(7.5,-2.5) U23(8.5,-2.5) U24(9.5,-2.5) U25(10.5,-2.5) U26(11.5,-2.5) U27(12.5,-2.5) U28(13.5,-2.5) V1(-13.5,-3.5) V2(-12.5,-3.5) V3(-11.5,-3.5) V4(-10.5,-3.5) V5(-9.5,-3.5) V6(-8.5,-3.5) V7(-7.5,-3.5) V8(-6.5,-3.5) V9(-5.5,-3.5) V10(-4.5,-3.5) V11(-3.5,-3.5) V12(-2.5,-3.5) V13(-1.5,-3.5) V14(-0.5,-3.5) V15(0.5,-3.5) V16(1.5,-3.5) V17(2.5,-3.5) V18(3.5,-3.5) V19(4.5,-3.5) V20(5.5,-3.5) V21(6.5,-3.5) V22(7.5,-3.5) V23(8.5,-3.5) V24(9.5,-3.5) V25(10.5,-3.5) V26(11.5,-3.5) V27(12.5,-3.5) V28(13.5,-3.5) W1(-13.5,-4.5) W2(-12.5,-4.5) W3(-11.5,-4.5) W4(-10.5,-4.5) W5(-9.5,-4.5) W6(-8.5,-4.5) W7(-7.5,-4.5) W8(-6.5,-4.5) W9(-5.5,-4.5) W10(-4.5,-4.5) W11(-3.5,-4.5) W12(-2.5,-4.5) W13(-1.5,-4.5) W14(-0.5,-4.5) W15(0.5,-4.5) W16(1.5,-4.5) W17(2.5,-4.5) W18(3.5,-4.5) W19(4.5,-4.5) W20(5.5,-4.5) W21(6.5,-4.5) W22(7.5,-4.5) W23(8.5,-4.5) W24(9.5,-4.5) W25(10.5,-4.5) W26(11.5,-4.5) W27(12.5,-4.5) W28(13.5,-4.5) Y1(-13.5,-5.5) Y2(-12.5,-5.5) Y3(-11.5,-5.5) Y4(-10.5,-5.5) Y5(-9.5,-5.5) Y6(-8.5,-5.5) Y7(-7.5,-5.5) Y8(-6.5,-5.5) Y9(-5.5,-5.5) Y10(-4.5,-5.5) Y11(-3.5,-5.5) Y12(-2.5,-5.5) Y13(-1.5,-5.5) Y14(-0.5,-5.5) Y15(0.5,-5.5) Y16(1.5,-5.5) Y17(2.5,-5.5) Y18(3.5,-5.5) Y19(4.5,-5.5) Y20(5.5,-5.5) Y21(6.5,-5.5) Y22(7.5,-5.5) Y23(8.5,-5.5) Y24(9.5,-5.5) Y25(10.5,-5.5) Y26(11.5,-5.5) Y27(12.5,-5.5) Y28(13.5,-5.5)
Top Overlay:
  circle w0.25: c-15.155,13.5 r0.125
  lines w0.2: -14.5,-13.5 -13.5,-14.5 13.5,-14.5 14.5,-13.5 14.5,13.5 13.5,14.5 -14.5,14.5 -14.5,-13.5

## BGA31X31-B841 [mm]
pads (841):
  round 0.5 smd: A1(-14,14) A2(-13,14) A3(-12,14) A4(-11,14) A5(-10,14) A6(-9,14) A7(-8,14) A8(-7,14) A9(-6,14) A10(-5,14) A11(-4,14) A12(-3,14) A13(-2,14) A14(-1,14) A15(0,14) A16(1,14) A17(2,14) A18(3,14) A19(4,14) A20(5,14) A21(6,14) A22(7,14) A23(8,14) A24(9,14) A25(10,14) A26(11,14) A27(12,14) A28(13,14) A29(14,14) AA1(-14,-6) AA2(-13,-6) AA3(-12,-6) AA4(-11,-6) AA5(-10,-6) AA6(-9,-6) AA7(-8,-6) AA8(-7,-6) AA9(-6,-6) AA10(-5,-6) AA11(-4,-6) AA12(-3,-6) AA13(-2,-6) AA14(-1,-6) AA15(0,-6) AA16(1,-6) AA17(2,-6) AA18(3,-6) AA19(4,-6) AA20(5,-6) AA21(6,-6) AA22(7,-6) AA23(8,-6) AA24(9,-6) AA25(10,-6) AA26(11,-6) AA27(12,-6) AA28(13,-6) AA29(14,-6) AB1(-14,-7) AB2(-13,-7) AB3(-12,-7) AB4(-11,-7) AB5(-10,-7) AB6(-9,-7) AB7(-8,-7) AB8(-7,-7) AB9(-6,-7) AB10(-5,-7) AB11(-4,-7) AB12(-3,-7) AB13(-2,-7) AB14(-1,-7) AB15(0,-7) AB16(1,-7) AB17(2,-7) AB18(3,-7) AB19(4,-7) AB20(5,-7) AB21(6,-7) AB22(7,-7) AB23(8,-7) AB24(9,-7) AB25(10,-7) AB26(11,-7) AB27(12,-7) AB28(13,-7) AB29(14,-7) AC1(-14,-8) AC2(-13,-8) AC3(-12,-8) AC4(-11,-8) AC5(-10,-8) AC6(-9,-8) AC7(-8,-8) AC8(-7,-8) AC9(-6,-8) AC10(-5,-8) AC11(-4,-8) AC12(-3,-8) AC13(-2,-8) AC14(-1,-8) AC15(0,-8) AC16(1,-8) AC17(2,-8) AC18(3,-8) AC19(4,-8) AC20(5,-8) AC21(6,-8) AC22(7,-8) AC23(8,-8) AC24(9,-8) AC25(10,-8) AC26(11,-8) AC27(12,-8) AC28(13,-8) AC29(14,-8) AD1(-14,-9) AD2(-13,-9) AD3(-12,-9) AD4(-11,-9) AD5(-10,-9) AD6(-9,-9) AD7(-8,-9) AD8(-7,-9) AD9(-6,-9) AD10(-5,-9) AD11(-4,-9) AD12(-3,-9) AD13(-2,-9) AD14(-1,-9) AD15(0,-9) AD16(1,-9) AD17(2,-9) AD18(3,-9) AD19(4,-9) AD20(5,-9) AD21(6,-9) AD22(7,-9) AD23(8,-9) AD24(9,-9) AD25(10,-9) AD26(11,-9) AD27(12,-9) AD28(13,-9) AD29(14,-9) AE1(-14,-10) AE2(-13,-10) AE3(-12,-10) AE4(-11,-10) AE5(-10,-10) AE6(-9,-10) AE7(-8,-10) AE8(-7,-10) AE9(-6,-10) AE10(-5,-10) AE11(-4,-10) AE12(-3,-10) AE13(-2,-10) AE14(-1,-10) AE15(0,-10) AE16(1,-10) AE17(2,-10) AE18(3,-10) AE19(4,-10) AE20(5,-10) AE21(6,-10) AE22(7,-10) AE23(8,-10) AE24(9,-10) AE25(10,-10) AE26(11,-10) AE27(12,-10) AE28(13,-10) AE29(14,-10) AF1(-14,-11) AF2(-13,-11) AF3(-12,-11) AF4(-11,-11) AF5(-10,-11) AF6(-9,-11) AF7(-8,-11) AF8(-7,-11) AF9(-6,-11) AF10(-5,-11) AF11(-4,-11) AF12(-3,-11) AF13(-2,-11) AF14(-1,-11) AF15(0,-11) AF16(1,-11) AF17(2,-11) AF18(3,-11) AF19(4,-11) AF20(5,-11) AF21(6,-11) AF22(7,-11) AF23(8,-11) AF24(9,-11) AF25(10,-11) AF26(11,-11) AF27(12,-11) AF28(13,-11) AF29(14,-11) AG1(-14,-12) AG2(-13,-12) AG3(-12,-12) AG4(-11,-12) AG5(-10,-12) AG6(-9,-12) AG7(-8,-12) AG8(-7,-12) AG9(-6,-12) AG10(-5,-12) AG11(-4,-12) AG12(-3,-12) AG13(-2,-12) AG14(-1,-12) AG15(0,-12) AG16(1,-12) AG17(2,-12) AG18(3,-12) AG19(4,-12) AG20(5,-12) AG21(6,-12) AG22(7,-12) AG23(8,-12) AG24(9,-12) AG25(10,-12) AG26(11,-12) AG27(12,-12) AG28(13,-12) AG29(14,-12) AH1(-14,-13) AH2(-13,-13) AH3(-12,-13) AH4(-11,-13) AH5(-10,-13) AH6(-9,-13) AH7(-8,-13) AH8(-7,-13) AH9(-6,-13) AH10(-5,-13) AH11(-4,-13) AH12(-3,-13) AH13(-2,-13) AH14(-1,-13) AH15(0,-13) AH16(1,-13) AH17(2,-13) AH18(3,-13) AH19(4,-13) AH20(5,-13) AH21(6,-13) AH22(7,-13) AH23(8,-13) AH24(9,-13) AH25(10,-13) AH26(11,-13) AH27(12,-13) AH28(13,-13) AH29(14,-13) AJ1(-14,-14) AJ2(-13,-14) AJ3(-12,-14) AJ4(-11,-14) AJ5(-10,-14) AJ6(-9,-14) AJ7(-8,-14) AJ8(-7,-14) AJ9(-6,-14) AJ10(-5,-14) AJ11(-4,-14) AJ12(-3,-14) AJ13(-2,-14) AJ14(-1,-14) AJ15(0,-14) AJ16(1,-14) AJ17(2,-14) AJ18(3,-14) AJ19(4,-14) AJ20(5,-14) AJ21(6,-14) AJ22(7,-14) AJ23(8,-14) AJ24(9,-14) AJ25(10,-14) AJ26(11,-14) AJ27(12,-14) AJ28(13,-14) AJ29(14,-14) B1(-14,13) B2(-13,13) B3(-12,13) B4(-11,13) B5(-10,13) B6(-9,13) B7(-8,13) B8(-7,13) B9(-6,13) B10(-5,13) B11(-4,13) B12(-3,13) B13(-2,13) B14(-1,13) B15(0,13) B16(1,13) B17(2,13) B18(3,13) B19(4,13) B20(5,13) B21(6,13) B22(7,13) B23(8,13) B24(9,13) B25(10,13) B26(11,13) B27(12,13) B28(13,13) B29(14,13) C1(-14,12) C2(-13,12) C3(-12,12) C4(-11,12) C5(-10,12) C6(-9,12) C7(-8,12) C8(-7,12) C9(-6,12) C10(-5,12) C11(-4,12) C12(-3,12) C13(-2,12) C14(-1,12) C15(0,12) C16(1,12) C17(2,12) C18(3,12) C19(4,12) C20(5,12) C21(6,12) C22(7,12) C23(8,12) C24(9,12) C25(10,12) C26(11,12) C27(12,12) C28(13,12) C29(14,12) D1(-14,11) D2(-13,11) D3(-12,11) D4(-11,11) D5(-10,11) D6(-9,11) D7(-8,11) D8(-7,11) D9(-6,11) D10(-5,11) D11(-4,11) D12(-3,11) D13(-2,11) D14(-1,11) D15(0,11) D16(1,11) D17(2,11) D18(3,11) D19(4,11) D20(5,11) D21(6,11) D22(7,11) D23(8,11) D24(9,11) D25(10,11) D26(11,11) D27(12,11) D28(13,11) D29(14,11) E1(-14,10) E2(-13,10) E3(-12,10) E4(-11,10) E5(-10,10) E6(-9,10) E7(-8,10) E8(-7,10) E9(-6,10) E10(-5,10) E11(-4,10) E12(-3,10) E13(-2,10) E14(-1,10) E15(0,10) E16(1,10) E17(2,10) E18(3,10) E19(4,10) E20(5,10) E21(6,10) E22(7,10) E23(8,10) E24(9,10) E25(10,10) E26(11,10) E27(12,10) E28(13,10) E29(14,10) F1(-14,9) F2(-13,9) F3(-12,9) F4(-11,9) F5(-10,9) F6(-9,9) F7(-8,9) F8(-7,9) F9(-6,9) F10(-5,9) F11(-4,9) F12(-3,9) F13(-2,9) F14(-1,9) F15(0,9) F16(1,9) F17(2,9) F18(3,9) F19(4,9) F20(5,9) F21(6,9) F22(7,9) F23(8,9) F24(9,9) F25(10,9) F26(11,9) F27(12,9) F28(13,9) F29(14,9) G1(-14,8) G2(-13,8) G3(-12,8) G4(-11,8) G5(-10,8) G6(-9,8) G7(-8,8) G8(-7,8) G9(-6,8) G10(-5,8) G11(-4,8) G12(-3,8) G13(-2,8) G14(-1,8) G15(0,8) G16(1,8) G17(2,8) G18(3,8) G19(4,8) G20(5,8) G21(6,8) G22(7,8) G23(8,8) G24(9,8) G25(10,8) G26(11,8) G27(12,8) G28(13,8) G29(14,8) H1(-14,7) H2(-13,7) H3(-12,7) H4(-11,7) H5(-10,7) H6(-9,7) H7(-8,7) H8(-7,7) H9(-6,7) H10(-5,7) H11(-4,7) H12(-3,7) H13(-2,7) H14(-1,7) H15(0,7) H16(1,7) H17(2,7) H18(3,7) H19(4,7) H20(5,7) H21(6,7) H22(7,7) H23(8,7) H24(9,7) H25(10,7) H26(11,7) H27(12,7) H28(13,7) H29(14,7) J1(-14,6) J2(-13,6) J3(-12,6) J4(-11,6) J5(-10,6) J6(-9,6) J7(-8,6) J8(-7,6) J9(-6,6) J10(-5,6) J11(-4,6) J12(-3,6) J13(-2,6) J14(-1,6) J15(0,6) J16(1,6) J17(2,6) J18(3,6) J19(4,6) J20(5,6) J21(6,6) J22(7,6) J23(8,6) J24(9,6) J25(10,6) J26(11,6) J27(12,6) J28(13,6) J29(14,6) K1(-14,5) K2(-13,5) K3(-12,5) K4(-11,5) K5(-10,5) K6(-9,5) K7(-8,5) K8(-7,5) K9(-6,5) K10(-5,5) K11(-4,5) K12(-3,5) K13(-2,5) K14(-1,5) K15(0,5) K16(1,5) K17(2,5) K18(3,5) K19(4,5) K20(5,5) K21(6,5) K22(7,5) K23(8,5) K24(9,5) K25(10,5) K26(11,5) K27(12,5) K28(13,5) K29(14,5) L1(-14,4) L2(-13,4) L3(-12,4) L4(-11,4) L5(-10,4) L6(-9,4) L7(-8,4) L8(-7,4) L9(-6,4) L10(-5,4) L11(-4,4) L12(-3,4) L13(-2,4) L14(-1,4) L15(0,4) L16(1,4) L17(2,4) L18(3,4) L19(4,4) L20(5,4) L21(6,4) L22(7,4) L23(8,4) L24(9,4) L25(10,4) L26(11,4) L27(12,4) L28(13,4) L29(14,4) M1(-14,3) M2(-13,3) M3(-12,3) M4(-11,3) M5(-10,3) M6(-9,3) M7(-8,3) M8(-7,3) M9(-6,3) M10(-5,3) M11(-4,3) M12(-3,3) M13(-2,3) M14(-1,3) M15(0,3) M16(1,3) M17(2,3) M18(3,3) M19(4,3) M20(5,3) M21(6,3) M22(7,3) M23(8,3) M24(9,3) M25(10,3) M26(11,3) M27(12,3) M28(13,3) M29(14,3) N1(-14,2) N2(-13,2) N3(-12,2) N4(-11,2) N5(-10,2) N6(-9,2) N7(-8,2) N8(-7,2) N9(-6,2) N10(-5,2) N11(-4,2) N12(-3,2) N13(-2,2) N14(-1,2) N15(0,2) N16(1,2) N17(2,2) N18(3,2) N19(4,2) N20(5,2) N21(6,2) N22(7,2) N23(8,2) N24(9,2) N25(10,2) N26(11,2) N27(12,2) N28(13,2) N29(14,2) P1(-14,1) P2(-13,1) P3(-12,1) P4(-11,1) P5(-10,1) P6(-9,1) P7(-8,1) P8(-7,1) P9(-6,1) P10(-5,1) P11(-4,1) P12(-3,1) P13(-2,1) P14(-1,1) P15(0,1) P16(1,1) P17(2,1) P18(3,1) P19(4,1) P20(5,1) P21(6,1) P22(7,1) P23(8,1) P24(9,1) P25(10,1) P26(11,1) P27(12,1) P28(13,1) P29(14,1) R1(-14,0) R2(-13,0) R3(-12,0) R4(-11,0) R5(-10,0) R6(-9,0) R7(-8,0) R8(-7,0) R9(-6,0) R10(-5,0) R11(-4,0) R12(-3,0) R13(-2,0) R14(-1,0) R15(0,0) R16(1,0) R17(2,0) R18(3,0) R19(4,0) R20(5,0) R21(6,0) R22(7,0) R23(8,0) R24(9,0) R25(10,0) R26(11,0) R27(12,0) R28(13,0) R29(14,0) T1(-14,-1) T2(-13,-1) T3(-12,-1) T4(-11,-1) T5(-10,-1) T6(-9,-1) T7(-8,-1) T8(-7,-1) T9(-6,-1) T10(-5,-1) T11(-4,-1) T12(-3,-1) T13(-2,-1) T14(-1,-1) T15(0,-1) T16(1,-1) T17(2,-1) T18(3,-1) T19(4,-1) T20(5,-1) T21(6,-1) T22(7,-1) T23(8,-1) T24(9,-1) T25(10,-1) T26(11,-1) T27(12,-1) T28(13,-1) T29(14,-1) U1(-14,-2) U2(-13,-2) U3(-12,-2) U4(-11,-2) U5(-10,-2) U6(-9,-2) U7(-8,-2) U8(-7,-2) U9(-6,-2) U10(-5,-2) U11(-4,-2) U12(-3,-2) U13(-2,-2) U14(-1,-2) U15(0,-2) U16(1,-2) U17(2,-2) U18(3,-2) U19(4,-2) U20(5,-2) U21(6,-2) U22(7,-2) U23(8,-2) U24(9,-2) U25(10,-2) U26(11,-2) U27(12,-2) U28(13,-2) U29(14,-2) V1(-14,-3) V2(-13,-3) V3(-12,-3) V4(-11,-3) V5(-10,-3) V6(-9,-3) V7(-8,-3) V8(-7,-3) V9(-6,-3) V10(-5,-3) V11(-4,-3) V12(-3,-3) V13(-2,-3) V14(-1,-3) V15(0,-3) V16(1,-3) V17(2,-3) V18(3,-3) V19(4,-3) V20(5,-3) V21(6,-3) V22(7,-3) V23(8,-3) V24(9,-3) V25(10,-3) V26(11,-3) V27(12,-3) V28(13,-3) V29(14,-3) W1(-14,-4) W2(-13,-4) W3(-12,-4) W4(-11,-4) W5(-10,-4) W6(-9,-4) W7(-8,-4) W8(-7,-4) W9(-6,-4) W10(-5,-4) W11(-4,-4) W12(-3,-4) W13(-2,-4) W14(-1,-4) W15(0,-4) W16(1,-4) W17(2,-4) W18(3,-4) W19(4,-4) W20(5,-4) W21(6,-4) W22(7,-4) W23(8,-4) W24(9,-4) W25(10,-4) W26(11,-4) W27(12,-4) W28(13,-4) W29(14,-4) Y1(-14,-5) Y2(-13,-5) Y3(-12,-5) Y4(-11,-5) Y5(-10,-5) Y6(-9,-5) Y7(-8,-5) Y8(-7,-5) Y9(-6,-5) Y10(-5,-5) Y11(-4,-5) Y12(-3,-5) Y13(-2,-5) Y14(-1,-5) Y15(0,-5) Y16(1,-5) Y17(2,-5) Y18(3,-5) Y19(4,-5) Y20(5,-5) Y21(6,-5) Y22(7,-5) Y23(8,-5) Y24(9,-5) Y25(10,-5) Y26(11,-5) Y27(12,-5) Y28(13,-5) Y29(14,-5)
Top Overlay:
  circle w0.25: c-16.155,14 r0.125
  lines w0.2: -15.5,-14.5 -15.5,15.5 14.5,15.5 15.5,14.5 15.5,-14.5 14.5,-15.5 -14.5,-15.5 -15.5,-14.5

## BGA31X31-B896 [mm]
pads (896):
  round 0.5 smd: A2(-13.5,14.5) A3(-12.5,14.5) A4(-11.5,14.5) A5(-10.5,14.5) A6(-9.5,14.5) A7(-8.5,14.5) A8(-7.5,14.5) A9(-6.5,14.5) A10(-5.5,14.5) A11(-4.5,14.5) A12(-3.5,14.5) A13(-2.5,14.5) A14(-1.5,14.5) A15(-0.5,14.5) A16(0.5,14.5) A17(1.5,14.5) A18(2.5,14.5) A19(3.5,14.5) A20(4.5,14.5) A21(5.5,14.5) A22(6.5,14.5) A23(7.5,14.5) A24(8.5,14.5) A25(9.5,14.5) A26(10.5,14.5) A27(11.5,14.5) A28(12.5,14.5) A29(13.5,14.5) AA1(-14.5,-5.5) AA2(-13.5,-5.5) AA3(-12.5,-5.5) AA4(-11.5,-5.5) AA5(-10.5,-5.5) AA6(-9.5,-5.5) AA7(-8.5,-5.5) AA8(-7.5,-5.5) AA9(-6.5,-5.5) AA10(-5.5,-5.5) AA11(-4.5,-5.5) AA12(-3.5,-5.5) AA13(-2.5,-5.5) AA14(-1.5,-5.5) AA15(-0.5,-5.5) AA16(0.5,-5.5) AA17(1.5,-5.5) AA18(2.5,-5.5) AA19(3.5,-5.5) AA20(4.5,-5.5) AA21(5.5,-5.5) AA22(6.5,-5.5) AA23(7.5,-5.5) AA24(8.5,-5.5) AA25(9.5,-5.5) AA26(10.5,-5.5) AA27(11.5,-5.5) AA28(12.5,-5.5) AA29(13.5,-5.5) AA30(14.5,-5.5) AB1(-14.5,-6.5) AB2(-13.5,-6.5) AB3(-12.5,-6.5) AB4(-11.5,-6.5) AB5(-10.5,-6.5) AB6(-9.5,-6.5) AB7(-8.5,-6.5) AB8(-7.5,-6.5) AB9(-6.5,-6.5) AB10(-5.5,-6.5) AB11(-4.5,-6.5) AB12(-3.5,-6.5) AB13(-2.5,-6.5) AB14(-1.5,-6.5) AB15(-0.5,-6.5) AB16(0.5,-6.5) AB17(1.5,-6.5) AB18(2.5,-6.5) AB19(3.5,-6.5) AB20(4.5,-6.5) AB21(5.5,-6.5) AB22(6.5,-6.5) AB23(7.5,-6.5) AB24(8.5,-6.5) AB25(9.5,-6.5) AB26(10.5,-6.5) AB27(11.5,-6.5) AB28(12.5,-6.5) AB29(13.5,-6.5) AB30(14.5,-6.5) AC1(-14.5,-7.5) AC2(-13.5,-7.5) AC3(-12.5,-7.5) AC4(-11.5,-7.5) AC5(-10.5,-7.5) AC6(-9.5,-7.5) AC7(-8.5,-7.5) AC8(-7.5,-7.5) AC9(-6.5,-7.5) AC10(-5.5,-7.5) AC11(-4.5,-7.5) AC12(-3.5,-7.5) AC13(-2.5,-7.5) AC14(-1.5,-7.5) AC15(-0.5,-7.5) AC16(0.5,-7.5) AC17(1.5,-7.5) AC18(2.5,-7.5) AC19(3.5,-7.5) AC20(4.5,-7.5) AC21(5.5,-7.5) AC22(6.5,-7.5) AC23(7.5,-7.5) AC24(8.5,-7.5) AC25(9.5,-7.5) AC26(10.5,-7.5) AC27(11.5,-7.5) AC28(12.5,-7.5) AC29(13.5,-7.5) AC30(14.5,-7.5) AD1(-14.5,-8.5) AD2(-13.5,-8.5) AD3(-12.5,-8.5) AD4(-11.5,-8.5) AD5(-10.5,-8.5) AD6(-9.5,-8.5) AD7(-8.5,-8.5) AD8(-7.5,-8.5) AD9(-6.5,-8.5) AD10(-5.5,-8.5) AD11(-4.5,-8.5) AD12(-3.5,-8.5) AD13(-2.5,-8.5) AD14(-1.5,-8.5) AD15(-0.5,-8.5) AD16(0.5,-8.5) AD17(1.5,-8.5) AD18(2.5,-8.5) AD19(3.5,-8.5) AD20(4.5,-8.5) AD21(5.5,-8.5) AD22(6.5,-8.5) AD23(7.5,-8.5) AD24(8.5,-8.5) AD25(9.5,-8.5) AD26(10.5,-8.5) AD27(11.5,-8.5) AD28(12.5,-8.5) AD29(13.5,-8.5) AD30(14.5,-8.5) AE1(-14.5,-9.5) AE2(-13.5,-9.5) AE3(-12.5,-9.5) AE4(-11.5,-9.5) AE5(-10.5,-9.5) AE6(-9.5,-9.5) AE7(-8.5,-9.5) AE8(-7.5,-9.5) AE9(-6.5,-9.5) AE10(-5.5,-9.5) AE11(-4.5,-9.5) AE12(-3.5,-9.5) AE13(-2.5,-9.5) AE14(-1.5,-9.5) AE15(-0.5,-9.5) AE16(0.5,-9.5) AE17(1.5,-9.5) AE18(2.5,-9.5) AE19(3.5,-9.5) AE20(4.5,-9.5) AE21(5.5,-9.5) AE22(6.5,-9.5) AE23(7.5,-9.5) AE24(8.5,-9.5) AE25(9.5,-9.5) AE26(10.5,-9.5) AE27(11.5,-9.5) AE28(12.5,-9.5) AE29(13.5,-9.5) AE30(14.5,-9.5) AF1(-14.5,-10.5) AF2(-13.5,-10.5) AF3(-12.5,-10.5) AF4(-11.5,-10.5) AF5(-10.5,-10.5) AF6(-9.5,-10.5) AF7(-8.5,-10.5) AF8(-7.5,-10.5) AF9(-6.5,-10.5) AF10(-5.5,-10.5) AF11(-4.5,-10.5) AF12(-3.5,-10.5) AF13(-2.5,-10.5) AF14(-1.5,-10.5) AF15(-0.5,-10.5) AF16(0.5,-10.5) AF17(1.5,-10.5) AF18(2.5,-10.5) AF19(3.5,-10.5) AF20(4.5,-10.5) AF21(5.5,-10.5) AF22(6.5,-10.5) AF23(7.5,-10.5) AF24(8.5,-10.5) AF25(9.5,-10.5) AF26(10.5,-10.5) AF27(11.5,-10.5) AF28(12.5,-10.5) AF29(13.5,-10.5) AF30(14.5,-10.5) AG1(-14.5,-11.5) AG2(-13.5,-11.5) AG3(-12.5,-11.5) AG4(-11.5,-11.5) AG5(-10.5,-11.5) AG6(-9.5,-11.5) AG7(-8.5,-11.5) AG8(-7.5,-11.5) AG9(-6.5,-11.5) AG10(-5.5,-11.5) AG11(-4.5,-11.5) AG12(-3.5,-11.5) AG13(-2.5,-11.5) AG14(-1.5,-11.5) AG15(-0.5,-11.5) AG16(0.5,-11.5) AG17(1.5,-11.5) AG18(2.5,-11.5) AG19(3.5,-11.5) AG20(4.5,-11.5) AG21(5.5,-11.5) AG22(6.5,-11.5) AG23(7.5,-11.5) AG24(8.5,-11.5) AG25(9.5,-11.5) AG26(10.5,-11.5) AG27(11.5,-11.5) AG28(12.5,-11.5) AG29(13.5,-11.5) AG30(14.5,-11.5) AH1(-14.5,-12.5) AH2(-13.5,-12.5) AH3(-12.5,-12.5) AH4(-11.5,-12.5) AH5(-10.5,-12.5) AH6(-9.5,-12.5) AH7(-8.5,-12.5) AH8(-7.5,-12.5) AH9(-6.5,-12.5) AH10(-5.5,-12.5) AH11(-4.5,-12.5) AH12(-3.5,-12.5) AH13(-2.5,-12.5) AH14(-1.5,-12.5) AH15(-0.5,-12.5) AH16(0.5,-12.5) AH17(1.5,-12.5) AH18(2.5,-12.5) AH19(3.5,-12.5) AH20(4.5,-12.5) AH21(5.5,-12.5) AH22(6.5,-12.5) AH23(7.5,-12.5) AH24(8.5,-12.5) AH25(9.5,-12.5) AH26(10.5,-12.5) AH27(11.5,-12.5) AH28(12.5,-12.5) AH29(13.5,-12.5) AH30(14.5,-12.5) AJ1(-14.5,-13.5) AJ2(-13.5,-13.5) AJ3(-12.5,-13.5) AJ4(-11.5,-13.5) AJ5(-10.5,-13.5) AJ6(-9.5,-13.5) AJ7(-8.5,-13.5) AJ8(-7.5,-13.5) AJ9(-6.5,-13.5) AJ10(-5.5,-13.5) AJ11(-4.5,-13.5) AJ12(-3.5,-13.5) AJ13(-2.5,-13.5) AJ14(-1.5,-13.5) AJ15(-0.5,-13.5) AJ16(0.5,-13.5) AJ17(1.5,-13.5) AJ18(2.5,-13.5) AJ19(3.5,-13.5) AJ20(4.5,-13.5) AJ21(5.5,-13.5) AJ22(6.5,-13.5) AJ23(7.5,-13.5) AJ24(8.5,-13.5) AJ25(9.5,-13.5) AJ26(10.5,-13.5) AJ27(11.5,-13.5) AJ28(12.5,-13.5) AJ29(13.5,-13.5) AJ30(14.5,-13.5) AK2(-13.5,-14.5) AK3(-12.5,-14.5) AK4(-11.5,-14.5) AK5(-10.5,-14.5) AK6(-9.5,-14.5) AK7(-8.5,-14.5) AK8(-7.5,-14.5) AK9(-6.5,-14.5) AK10(-5.5,-14.5) AK11(-4.5,-14.5) AK12(-3.5,-14.5) AK13(-2.5,-14.5) AK14(-1.5,-14.5) AK15(-0.5,-14.5) AK16(0.5,-14.5) AK17(1.5,-14.5) AK18(2.5,-14.5) AK19(3.5,-14.5) AK20(4.5,-14.5) AK21(5.5,-14.5) AK22(6.5,-14.5) AK23(7.5,-14.5) AK24(8.5,-14.5) AK25(9.5,-14.5) AK26(10.5,-14.5) AK27(11.5,-14.5) AK28(12.5,-14.5) AK29(13.5,-14.5) B1(-14.5,13.5) B2(-13.5,13.5) B3(-12.5,13.5) B4(-11.5,13.5) B5(-10.5,13.5) B6(-9.5,13.5) B7(-8.5,13.5) B8(-7.5,13.5) B9(-6.5,13.5) B10(-5.5,13.5) B11(-4.5,13.5) B12(-3.5,13.5) B13(-2.5,13.5) B14(-1.5,13.5) B15(-0.5,13.5) B16(0.5,13.5) B17(1.5,13.5) B18(2.5,13.5) B19(3.5,13.5) B20(4.5,13.5) B21(5.5,13.5) B22(6.5,13.5) B23(7.5,13.5) B24(8.5,13.5) B25(9.5,13.5) B26(10.5,13.5) B27(11.5,13.5) B28(12.5,13.5) B29(13.5,13.5) B30(14.5,13.5) C1(-14.5,12.5) C2(-13.5,12.5) C3(-12.5,12.5) C4(-11.5,12.5) C5(-10.5,12.5) C6(-9.5,12.5) C7(-8.5,12.5) C8(-7.5,12.5) C9(-6.5,12.5) C10(-5.5,12.5) C11(-4.5,12.5) C12(-3.5,12.5) C13(-2.5,12.5) C14(-1.5,12.5) C15(-0.5,12.5) C16(0.5,12.5) C17(1.5,12.5) C18(2.5,12.5) C19(3.5,12.5) C20(4.5,12.5) C21(5.5,12.5) C22(6.5,12.5) C23(7.5,12.5) C24(8.5,12.5) C25(9.5,12.5) C26(10.5,12.5) C27(11.5,12.5) C28(12.5,12.5) C29(13.5,12.5) C30(14.5,12.5) D1(-14.5,11.5) D2(-13.5,11.5) D3(-12.5,11.5) D4(-11.5,11.5) D5(-10.5,11.5) D6(-9.5,11.5) D7(-8.5,11.5) D8(-7.5,11.5) D9(-6.5,11.5) D10(-5.5,11.5) D11(-4.5,11.5) D12(-3.5,11.5) D13(-2.5,11.5) D14(-1.5,11.5) D15(-0.5,11.5) D16(0.5,11.5) D17(1.5,11.5) D18(2.5,11.5) D19(3.5,11.5) D20(4.5,11.5) D21(5.5,11.5) D22(6.5,11.5) D23(7.5,11.5) D24(8.5,11.5) D25(9.5,11.5) D26(10.5,11.5) D27(11.5,11.5) D28(12.5,11.5) D29(13.5,11.5) D30(14.5,11.5) E1(-14.5,10.5) E2(-13.5,10.5) E3(-12.5,10.5) E4(-11.5,10.5) E5(-10.5,10.5) E6(-9.5,10.5) E7(-8.5,10.5) E8(-7.5,10.5) E9(-6.5,10.5) E10(-5.5,10.5) E11(-4.5,10.5) E12(-3.5,10.5) E13(-2.5,10.5) E14(-1.5,10.5) E15(-0.5,10.5) E16(0.5,10.5) E17(1.5,10.5) E18(2.5,10.5) E19(3.5,10.5) E20(4.5,10.5) E21(5.5,10.5) E22(6.5,10.5) E23(7.5,10.5) E24(8.5,10.5) E25(9.5,10.5) E26(10.5,10.5) E27(11.5,10.5) E28(12.5,10.5) E29(13.5,10.5) E30(14.5,10.5) F1(-14.5,9.5) F2(-13.5,9.5) F3(-12.5,9.5) F4(-11.5,9.5) F5(-10.5,9.5) F6(-9.5,9.5) F7(-8.5,9.5) F8(-7.5,9.5) F9(-6.5,9.5) F10(-5.5,9.5) F11(-4.5,9.5) F12(-3.5,9.5) F13(-2.5,9.5) F14(-1.5,9.5) F15(-0.5,9.5) F16(0.5,9.5) F17(1.5,9.5) F18(2.5,9.5) F19(3.5,9.5) F20(4.5,9.5) F21(5.5,9.5) F22(6.5,9.5) F23(7.5,9.5) F24(8.5,9.5) F25(9.5,9.5) F26(10.5,9.5) F27(11.5,9.5) F28(12.5,9.5) F29(13.5,9.5) F30(14.5,9.5) G1(-14.5,8.5) G2(-13.5,8.5) G3(-12.5,8.5) G4(-11.5,8.5) G5(-10.5,8.5) G6(-9.5,8.5) G7(-8.5,8.5) G8(-7.5,8.5) G9(-6.5,8.5) G10(-5.5,8.5) G11(-4.5,8.5) G12(-3.5,8.5) G13(-2.5,8.5) G14(-1.5,8.5) G15(-0.5,8.5) G16(0.5,8.5) G17(1.5,8.5) G18(2.5,8.5) G19(3.5,8.5) G20(4.5,8.5) G21(5.5,8.5) G22(6.5,8.5) G23(7.5,8.5) G24(8.5,8.5) G25(9.5,8.5) G26(10.5,8.5) G27(11.5,8.5) G28(12.5,8.5) G29(13.5,8.5) G30(14.5,8.5) H1(-14.5,7.5) H2(-13.5,7.5) H3(-12.5,7.5) H4(-11.5,7.5) H5(-10.5,7.5) H6(-9.5,7.5) H7(-8.5,7.5) H8(-7.5,7.5) H9(-6.5,7.5) H10(-5.5,7.5) H11(-4.5,7.5) H12(-3.5,7.5) H13(-2.5,7.5) H14(-1.5,7.5) H15(-0.5,7.5) H16(0.5,7.5) H17(1.5,7.5) H18(2.5,7.5) H19(3.5,7.5) H20(4.5,7.5) H21(5.5,7.5) H22(6.5,7.5) H23(7.5,7.5) H24(8.5,7.5) H25(9.5,7.5) H26(10.5,7.5) H27(11.5,7.5) H28(12.5,7.5) H29(13.5,7.5) H30(14.5,7.5) J1(-14.5,6.5) J2(-13.5,6.5) J3(-12.5,6.5) J4(-11.5,6.5) J5(-10.5,6.5) J6(-9.5,6.5) J7(-8.5,6.5) J8(-7.5,6.5) J9(-6.5,6.5) J10(-5.5,6.5) J11(-4.5,6.5) J12(-3.5,6.5) J13(-2.5,6.5) J14(-1.5,6.5) J15(-0.5,6.5) J16(0.5,6.5) J17(1.5,6.5) J18(2.5,6.5) J19(3.5,6.5) J20(4.5,6.5) J21(5.5,6.5) J22(6.5,6.5) J23(7.5,6.5) J24(8.5,6.5) J25(9.5,6.5) J26(10.5,6.5) J27(11.5,6.5) J28(12.5,6.5) J29(13.5,6.5) J30(14.5,6.5) K1(-14.5,5.5) K2(-13.5,5.5) K3(-12.5,5.5) K4(-11.5,5.5) K5(-10.5,5.5) K6(-9.5,5.5) K7(-8.5,5.5) K8(-7.5,5.5) K9(-6.5,5.5) K10(-5.5,5.5) K11(-4.5,5.5) K12(-3.5,5.5) K13(-2.5,5.5) K14(-1.5,5.5) K15(-0.5,5.5) K16(0.5,5.5) K17(1.5,5.5) K18(2.5,5.5) K19(3.5,5.5) K20(4.5,5.5) K21(5.5,5.5) K22(6.5,5.5) K23(7.5,5.5) K24(8.5,5.5) K25(9.5,5.5) K26(10.5,5.5) K27(11.5,5.5) K28(12.5,5.5) K29(13.5,5.5) K30(14.5,5.5) L1(-14.5,4.5) L2(-13.5,4.5) L3(-12.5,4.5) L4(-11.5,4.5) L5(-10.5,4.5) L6(-9.5,4.5) L7(-8.5,4.5) L8(-7.5,4.5) L9(-6.5,4.5) L10(-5.5,4.5) L11(-4.5,4.5) L12(-3.5,4.5) L13(-2.5,4.5) L14(-1.5,4.5) L15(-0.5,4.5) L16(0.5,4.5) L17(1.5,4.5) L18(2.5,4.5) L19(3.5,4.5) L20(4.5,4.5) L21(5.5,4.5) L22(6.5,4.5) L23(7.5,4.5) L24(8.5,4.5) L25(9.5,4.5) L26(10.5,4.5) L27(11.5,4.5) L28(12.5,4.5) L29(13.5,4.5) L30(14.5,4.5) M1(-14.5,3.5) M2(-13.5,3.5) M3(-12.5,3.5) M4(-11.5,3.5) M5(-10.5,3.5) M6(-9.5,3.5) M7(-8.5,3.5) M8(-7.5,3.5) M9(-6.5,3.5) M10(-5.5,3.5) M11(-4.5,3.5) M12(-3.5,3.5) M13(-2.5,3.5) M14(-1.5,3.5) M15(-0.5,3.5) M16(0.5,3.5) M17(1.5,3.5) M18(2.5,3.5) M19(3.5,3.5) M20(4.5,3.5) M21(5.5,3.5) M22(6.5,3.5) M23(7.5,3.5) M24(8.5,3.5) M25(9.5,3.5) M26(10.5,3.5) M27(11.5,3.5) M28(12.5,3.5) M29(13.5,3.5) M30(14.5,3.5) N1(-14.5,2.5) N2(-13.5,2.5) N3(-12.5,2.5) N4(-11.5,2.5) N5(-10.5,2.5) N6(-9.5,2.5) N7(-8.5,2.5) N8(-7.5,2.5) N9(-6.5,2.5) N10(-5.5,2.5) N11(-4.5,2.5) N12(-3.5,2.5) N13(-2.5,2.5) N14(-1.5,2.5) N15(-0.5,2.5) N16(0.5,2.5) N17(1.5,2.5) N18(2.5,2.5) N19(3.5,2.5) N20(4.5,2.5) N21(5.5,2.5) N22(6.5,2.5) N23(7.5,2.5) N24(8.5,2.5) N25(9.5,2.5) N26(10.5,2.5) N27(11.5,2.5) N28(12.5,2.5) N29(13.5,2.5) N30(14.5,2.5) P1(-14.5,1.5) P2(-13.5,1.5) P3(-12.5,1.5) P4(-11.5,1.5) P5(-10.5,1.5) P6(-9.5,1.5) P7(-8.5,1.5) P8(-7.5,1.5) P9(-6.5,1.5) P10(-5.5,1.5) P11(-4.5,1.5) P12(-3.5,1.5) P13(-2.5,1.5) P14(-1.5,1.5) P15(-0.5,1.5) P16(0.5,1.5) P17(1.5,1.5) P18(2.5,1.5) P19(3.5,1.5) P20(4.5,1.5) P21(5.5,1.5) P22(6.5,1.5) P23(7.5,1.5) P24(8.5,1.5) P25(9.5,1.5) P26(10.5,1.5) P27(11.5,1.5) P28(12.5,1.5) P29(13.5,1.5) P30(14.5,1.5) R1(-14.5,0.5) R2(-13.5,0.5) R3(-12.5,0.5) R4(-11.5,0.5) R5(-10.5,0.5) R6(-9.5,0.5) R7(-8.5,0.5) R8(-7.5,0.5) R9(-6.5,0.5) R10(-5.5,0.5) R11(-4.5,0.5) R12(-3.5,0.5) R13(-2.5,0.5) R14(-1.5,0.5) R15(-0.5,0.5) R16(0.5,0.5) R17(1.5,0.5) R18(2.5,0.5) R19(3.5,0.5) R20(4.5,0.5) R21(5.5,0.5) R22(6.5,0.5) R23(7.5,0.5) R24(8.5,0.5) R25(9.5,0.5) R26(10.5,0.5) R27(11.5,0.5) R28(12.5,0.5) R29(13.5,0.5) R30(14.5,0.5) T1(-14.5,-0.5) T2(-13.5,-0.5) T3(-12.5,-0.5) T4(-11.5,-0.5) T5(-10.5,-0.5) T6(-9.5,-0.5) T7(-8.5,-0.5) T8(-7.5,-0.5) T9(-6.5,-0.5) T10(-5.5,-0.5) T11(-4.5,-0.5) T12(-3.5,-0.5) T13(-2.5,-0.5) T14(-1.5,-0.5) T15(-0.5,-0.5) T16(0.5,-0.5) T17(1.5,-0.5) T18(2.5,-0.5) T19(3.5,-0.5) T20(4.5,-0.5) T21(5.5,-0.5) T22(6.5,-0.5) T23(7.5,-0.5) T24(8.5,-0.5) T25(9.5,-0.5) T26(10.5,-0.5) T27(11.5,-0.5) T28(12.5,-0.5) T29(13.5,-0.5) T30(14.5,-0.5) U1(-14.5,-1.5) U2(-13.5,-1.5) U3(-12.5,-1.5) U4(-11.5,-1.5) U5(-10.5,-1.5) U6(-9.5,-1.5) U7(-8.5,-1.5) U8(-7.5,-1.5) U9(-6.5,-1.5) U10(-5.5,-1.5) U11(-4.5,-1.5) U12(-3.5,-1.5) U13(-2.5,-1.5) U14(-1.5,-1.5) U15(-0.5,-1.5) U16(0.5,-1.5) U17(1.5,-1.5) U18(2.5,-1.5) U19(3.5,-1.5) U20(4.5,-1.5) U21(5.5,-1.5) U22(6.5,-1.5) U23(7.5,-1.5) U24(8.5,-1.5) U25(9.5,-1.5) U26(10.5,-1.5) U27(11.5,-1.5) U28(12.5,-1.5) U29(13.5,-1.5) U30(14.5,-1.5) V1(-14.5,-2.5) V2(-13.5,-2.5) V3(-12.5,-2.5) V4(-11.5,-2.5) V5(-10.5,-2.5) V6(-9.5,-2.5) V7(-8.5,-2.5) V8(-7.5,-2.5) V9(-6.5,-2.5) V10(-5.5,-2.5) V11(-4.5,-2.5) V12(-3.5,-2.5) V13(-2.5,-2.5) V14(-1.5,-2.5) V15(-0.5,-2.5) V16(0.5,-2.5) V17(1.5,-2.5) V18(2.5,-2.5) V19(3.5,-2.5) V20(4.5,-2.5) V21(5.5,-2.5) V22(6.5,-2.5) V23(7.5,-2.5) V24(8.5,-2.5) V25(9.5,-2.5) V26(10.5,-2.5) V27(11.5,-2.5) V28(12.5,-2.5) V29(13.5,-2.5) V30(14.5,-2.5) W1(-14.5,-3.5) W2(-13.5,-3.5) W3(-12.5,-3.5) W4(-11.5,-3.5) W5(-10.5,-3.5) W6(-9.5,-3.5) W7(-8.5,-3.5) W8(-7.5,-3.5) W9(-6.5,-3.5) W10(-5.5,-3.5) W11(-4.5,-3.5) W12(-3.5,-3.5) W13(-2.5,-3.5) W14(-1.5,-3.5) W15(-0.5,-3.5) W16(0.5,-3.5) W17(1.5,-3.5) W18(2.5,-3.5) W19(3.5,-3.5) W20(4.5,-3.5) W21(5.5,-3.5) W22(6.5,-3.5) W23(7.5,-3.5) W24(8.5,-3.5) W25(9.5,-3.5) W26(10.5,-3.5) W27(11.5,-3.5) W28(12.5,-3.5) W29(13.5,-3.5) W30(14.5,-3.5) Y1(-14.5,-4.5) Y2(-13.5,-4.5) Y3(-12.5,-4.5) Y4(-11.5,-4.5) Y5(-10.5,-4.5) Y6(-9.5,-4.5) Y7(-8.5,-4.5) Y8(-7.5,-4.5) Y9(-6.5,-4.5) Y10(-5.5,-4.5) Y11(-4.5,-4.5) Y12(-3.5,-4.5) Y13(-2.5,-4.5) Y14(-1.5,-4.5) Y15(-0.5,-4.5) Y16(0.5,-4.5) Y17(1.5,-4.5) Y18(2.5,-4.5) Y19(3.5,-4.5) Y20(4.5,-4.5) Y21(5.5,-4.5) Y22(6.5,-4.5) Y23(7.5,-4.5) Y24(8.5,-4.5) Y25(9.5,-4.5) Y26(10.5,-4.5) Y27(11.5,-4.5) Y28(12.5,-4.5) Y29(13.5,-4.5) Y30(14.5,-4.5)
Top Overlay:
  circle w0.25: c-16.15,14.5 r0.125
  lines w0.2: -15.5,-14.5 -14.5,-15.5 14.5,-15.5 15.5,-14.5 15.5,14.5 14.5,15.5 -15.5,15.5 -15.5,-14.5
